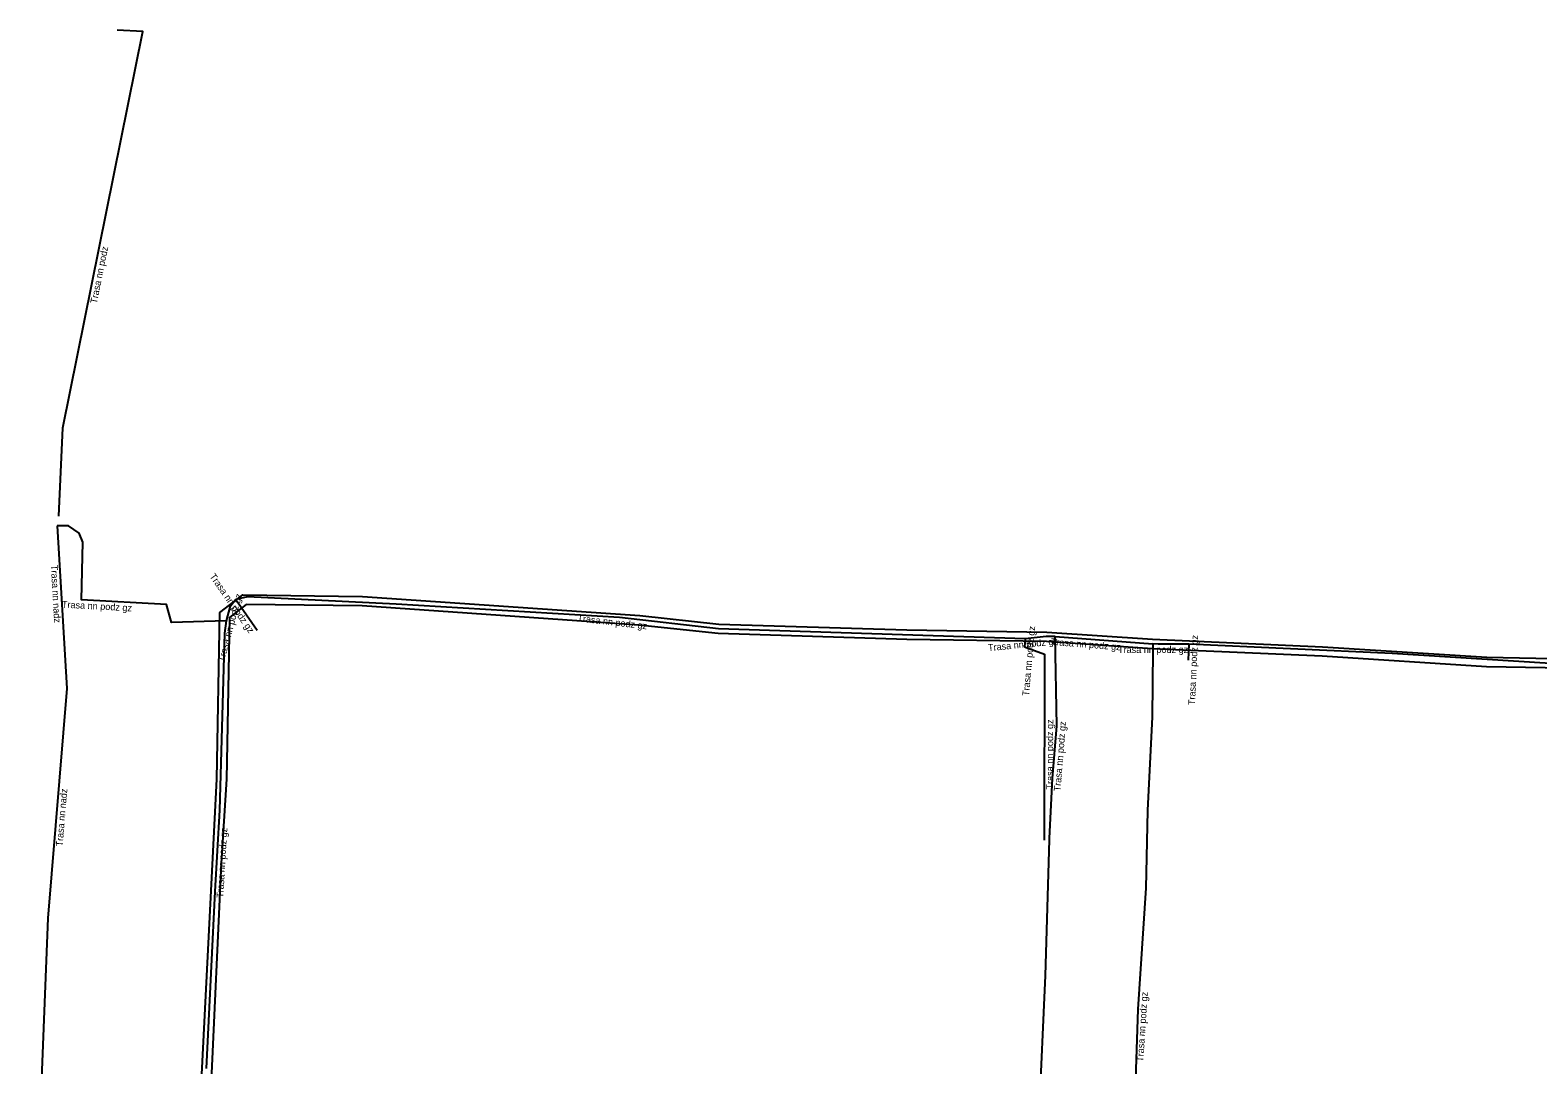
# Model space of a CAD drawing. Extents: x -747038 to -746494, y -1019526 to -1019195.
# Drawn here: x -746717.8 to -746606.8, y -1019285.5 to -1019209.3 of the extents above; entities that cross this region are included whole.
import ezdxf

# ---------------------------------------------------------------- set-up
doc = ezdxf.new("R2010")
doc.units = 0
for name, color, linetype in [('Popiskový text - Ostatní atributy Trasy', 7, 'Continuous'), ('Spojnice NN', 7, 'Continuous'), ('Spojnice VN', 7, 'Continuous')]:
    doc.layers.add(name, color=color, linetype=linetype)

msp = doc.modelspace()

# ---------------------------------------------------------------- linework, layer by layer
at = {"layer": 'Spojnice NN'}
for points in [[(-746715.68, -1019245.1), (-746715.4, -1019238.6), (-746709.5, -1019209.4), (-746711.4, -1019209.3)], [(-746703.36, -1019252.8), (-746707.4, -1019252.92), (-746707.76, -1019251.6), (-746714.01, -1019251.26), (-746713.91, -1019247.02), (-746714.18, -1019246.36), (-746714.98, -1019245.82), (-746715.8, -1019245.8)], [(-746715.8, -1019245.8), (-746715.1, -1019257.8)], [(-746702.64, -1019251.23), (-746703.1, -1019251.8), (-746703.36, -1019252.8)], [(-746644.51, -1019254.12), (-746667.1, -1019253.4), (-746674.39, -1019252.55), (-746690.85, -1019251.59), (-746701.79, -1019251.04), (-746702.64, -1019251.23)], [(-746702.64, -1019251.23), (-746701.07, -1019253.49)], [(-746703.36, -1019252.8), (-746703.49, -1019253.72), (-746703.86, -1019266.76), (-746704.21, -1019272.74), (-746704.83, -1019285.79)], [(-746642.32, -1019253.95), (-746642.59, -1019253.96), (-746642.98, -1019253.97), (-746644.51, -1019254.12)], [(-746642.72, -1019268.94), (-746642.72, -1019268.82), (-746642.5, -1019264.41), (-746642.19, -1019260.55), (-746642.32, -1019253.95)], [(-746642.32, -1019253.95), (-746635.11, -1019254.51)], [(-746644.51, -1019254.12), (-746644.57, -1019254.72)], [(-746644.57, -1019254.72), (-746643.1, -1019255.26), (-746643.11, -1019268.96)], [(-746635.11, -1019254.51), (-746635.12, -1019255), (-746635.16, -1019259.87), (-746635.5, -1019266.78), (-746635.64, -1019272.49), (-746636.21, -1019281.42), (-746636.57, -1019291.77), (-746636.83, -1019297.61), (-746637.36, -1019307.9), (-746637.38, -1019308.24)], [(-746632.46, -1019254.52), (-746634.73, -1019254.52), (-746635.11, -1019254.51)], [(-746632.46, -1019254.52), (-746632.51, -1019255.7)], [(-746566.72, -1019257.44), (-746586.08, -1019256.68), (-746601.56, -1019256.22), (-746617.48, -1019255.22), (-746632.46, -1019254.52)], [(-746715.1, -1019257.8), (-746716.5, -1019274.7)], [(-746644.67, -1019320.74), (-746644.27, -1019307.9), (-746644.07, -1019302.09), (-746643.48, -1019289.3), (-746643.01, -1019278.93), (-746642.72, -1019268.94)], [(-746716.5, -1019274.7), (-746717.8, -1019307.7)]]:
    msp.add_lwpolyline(points, dxfattribs=at)
at = {"layer": 'Spojnice VN'}
for points in [[(-746707.88, -1019364.86), (-746707.28, -1019358.02), (-746707.09, -1019352.25), (-746707.09, -1019338.31), (-746706.59, -1019333.08), (-746706.27, -1019314.24), (-746705.74, -1019305.37), (-746705.2, -1019287.19), (-746704.05, -1019264.46), (-746703.82, -1019252.2), (-746702.14, -1019250.9), (-746693.32, -1019251.01)], [(-746693.34, -1019251.71), (-746701.9, -1019251.6), (-746703.12, -1019252.55), (-746703.35, -1019264.48), (-746703.73, -1019270.65), (-746704.5, -1019287.21), (-746705.04, -1019305.4), (-746705.57, -1019314.27), (-746705.89, -1019333.12), (-746706.39, -1019338.35), (-746706.39, -1019352.26), (-746706.58, -1019358.06), (-746707.18, -1019364.91)], [(-746603.35, -1019256.32), (-746610.55, -1019256.19), (-746622.64, -1019255.41), (-746635.17, -1019254.86), (-746642.96, -1019254.33), (-746653.24, -1019254.18), (-746667.13, -1019253.75), (-746672.96, -1019253.12), (-746693.34, -1019251.71)], [(-746693.32, -1019251.01), (-746672.9, -1019252.42), (-746667.08, -1019253.05), (-746653.23, -1019253.48), (-746642.93, -1019253.63), (-746635.13, -1019254.16), (-746622.61, -1019254.71), (-746610.52, -1019255.49), (-746603.31, -1019255.62)]]:
    msp.add_lwpolyline(points, dxfattribs=at)

# ---------------------------------------------------------------- texts
at = {"layer": 'Popiskový text - Ostatní atributy Trasy'}
for s, rotation, p in [('Trasa nn podz', 78.5769, (-746712.89, -1019229.47)), ('Trasa nn nadz', 273.3385, (-746716.28, -1019248.7)), ('Trasa nn podz gz', 304.7584, (-746704.61, -1019249.53)), ('Trasa nn podz gz', 356.8887, (-746715.47, -1019251.83)), ('Trasa nn podz gz', 75.2877, (-746703.5, -1019255.87)), ('Trasa nn podz gz', 353.3476, (-746677.52, -1019252.84)), ('Trasa nn podz gz', 84.8657, (-746644.24, -1019258.36)), ('Trasa nn podz gz', 87.4746, (-746632.01, -1019259.02)), ('Trasa nn podz gz', 5.5001, (-746647.23, -1019255.04)), ('Trasa nn podz gz', 355.5436, (-746642.65, -1019254.58)), ('Trasa nn podz gz', 0.1263, (-746637.68, -1019255.18)), ('Trasa nn podz gz', 89.9592, (-746642.46, -1019265.23)), ('Trasa nn podz gz', 85.3753, (-746641.92, -1019265.38)), ('Trasa nn nadz', 85.2644, (-746715.41, -1019269.44)), ('Trasa nn podz gz', 86.6482, (-746703.58, -1019273.22)), ('Trasa nn podz gz', 86.2814, (-746635.82, -1019285.3))]:
    msp.add_text(s, height=0.5, rotation=rotation, dxfattribs=at).set_placement(p)

doc.saveas('drawing.dxf')
